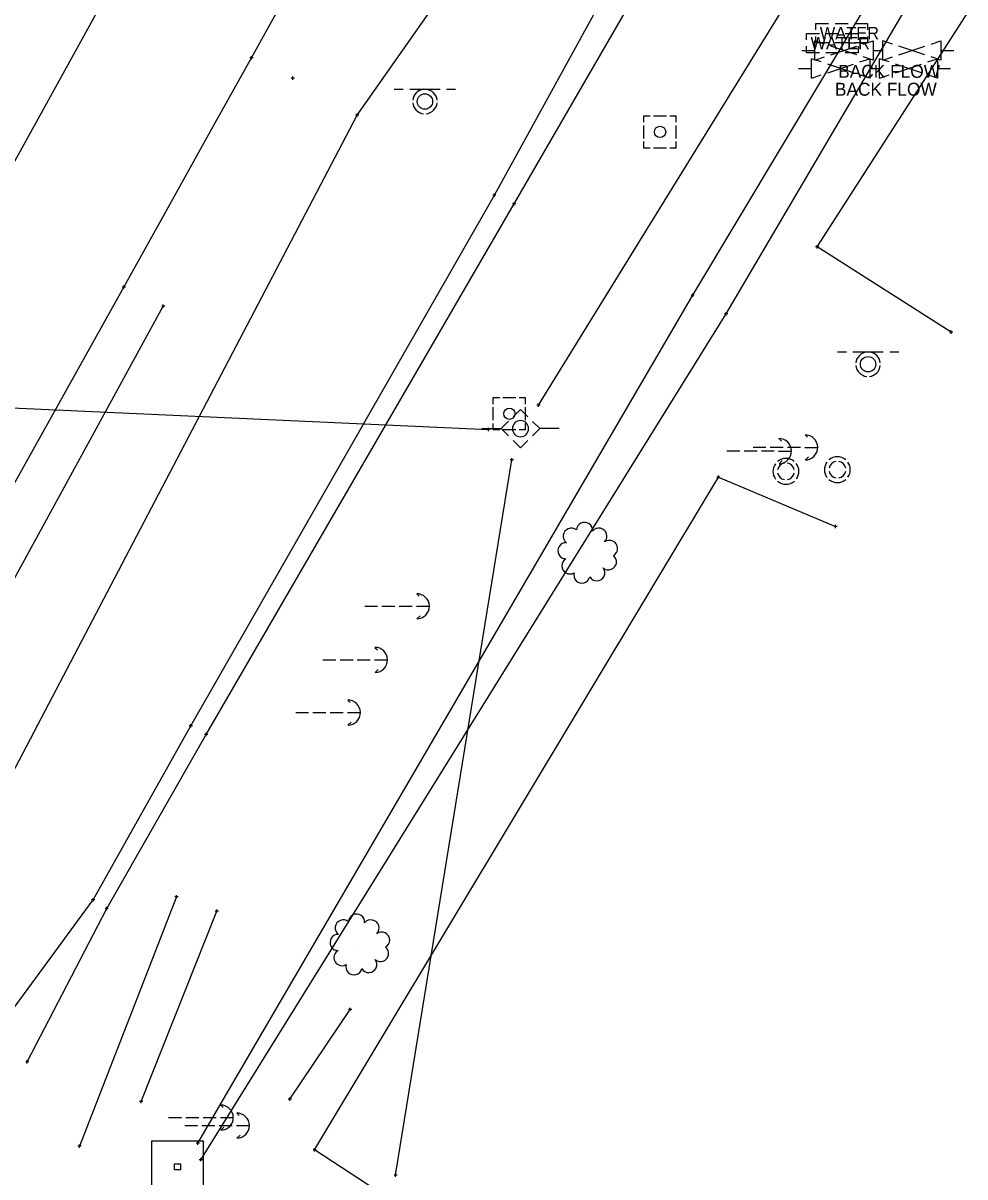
# Model space of a CAD drawing. Extents: x 1954856 to 2011933, y 399149 to 426294.
# Drawn here: x 2006422.5 to 2006495.3, y 401814.9 to 401904.2 of the extents above; entities that cross this region are included whole.
import ezdxf

# ---------------------------------------------------------------- set-up
doc = ezdxf.new("R2010")
doc.units = 0
for name, color, linetype in [('BankMent_ep', 7, 'Continuous'), ('Bollard_ep', 7, 'Continuous'), ('Driveway_ep', 7, 'Continuous'), ('ElecAer_ep', 7, 'Continuous'), ('GuyWireAnchor_ep', 7, 'Continuous'), ('MeterWater_ep', 7, 'Continuous'), ('MonumentCC_ep', 7, 'Continuous'), ('PavtAsphalt_ep', 7, 'Continuous'), ('PMRK_ep', 7, 'Continuous'), ('PointLocator_ep', 7, 'Continuous'), ('PoleShared_ep', 7, 'Continuous'), ('ShldrPaved_ep', 7, 'Continuous'), ('ShrubHedge_ep', 7, 'Continuous'), ('SignMulti_ep', 7, 'Continuous'), ('SignSingle_ep', 7, 'Continuous'), ('TelePed_ep', 7, 'Continuous'), ('TreeOak_ep', 7, 'Continuous'), ('ValveBFP_ep', 7, 'Continuous')]:
    doc.layers.add(name, color=color, linetype=linetype)

msp = doc.modelspace()

# ---------------------------------------------------------------- linework, layer by layer
at = {"layer": 'BankMent_ep'}
for p, q in [((2006448.304, 401897.038), (2006491.823, 401959.082)), ((2006474.251, 401883.114), (2006507.912, 401939.302)), ((2006411.686, 401827.146), (2006448.304, 401897.038)), ((2006435.982, 401817.55), (2006474.251, 401883.114)), ((2006434.331, 401836.603), (2006426.838, 401817.318)), ((2006431.602, 401820.765), (2006437.459, 401835.501))]:
    msp.add_line(p, q, dxfattribs=at)
for points in [[(2006419.806, 401825.353), (2006427.887, 401836.374), (2006435.44, 401849.828), (2006458.914, 401890.845), (2006490.387, 401948.13)], [(2006422.797, 401823.843), (2006428.939, 401835.689), (2006436.625, 401849.155), (2006460.454, 401890.17), (2006493.115, 401946.608)]]:
    msp.add_lwpolyline(points, dxfattribs=at)
at = {"layer": 'Bollard_ep'}
for p, q in [((2006481.46, 401869.499), (2006481.46, 401869.499)), ((2006485.441, 401869.627), (2006485.441, 401869.627))]:
    msp.add_line(p, q, dxfattribs=at)
for centre, radius, start, end in [((2006481.46, 401869.499), 1, 144.06538, 216.38889), ((2006481.46, 401869.499), 1, 49.51375, 130.94053), ((2006481.46, 401869.499), 0.65, 100.12662, 169.87338), ((2006481.46, 401869.499), 0.65, 10.12662, 79.87338), ((2006481.46, 401869.499), 1, 324.06538, 36.38889), ((2006485.441, 401869.627), 1, 144.06538, 216.38889), ((2006485.441, 401869.627), 1, 49.51375, 130.94053), ((2006485.441, 401869.627), 0.65, 100.12662, 169.87338), ((2006485.441, 401869.627), 0.65, 10.12662, 79.87338), ((2006485.441, 401869.627), 1, 324.06538, 36.38889), ((2006481.46, 401869.499), 0.65, 190.12662, 259.87338), ((2006481.46, 401869.499), 0.65, 280.12662, 349.87338), ((2006485.441, 401869.627), 0.65, 190.12662, 259.87338), ((2006485.441, 401869.627), 0.65, 280.12662, 349.87338), ((2006481.46, 401869.499), 1, 229.51375, 310.94053), ((2006485.441, 401869.627), 1, 229.51375, 310.94053)]:
    msp.add_arc(centre, radius, start, end, dxfattribs=at)
at = {"layer": 'Driveway_ep'}
for p, q in [((2006483.871, 401886.858), (2006521.346, 401945.083)), ((2006494.238, 401880.266), (2006483.871, 401886.858))]:
    msp.add_line(p, q, dxfattribs=at)
msp.add_lwpolyline([(2006452.014, 401812.452), (2006445.017, 401817.043), (2006476.238, 401869.059), (2006485.307, 401865.241)], dxfattribs=at)
at = {"layer": 'ElecAer_ep'}
for points in [[(2006462.324, 401874.616), (2006534.112, 401990.988)], [(2006212.402, 401883.926), (2006458.459, 401872.732)], [(2006451.282, 401815.07), (2006460.269, 401870.389)]]:
    msp.add_lwpolyline(points, dxfattribs=at)
at = {"layer": 'GuyWireAnchor_ep'}
for p, q in [((2006480.921, 401872.037), (2006481.114, 401871.844)), ((2006482.943, 401872.321), (2006483.136, 401872.128)), ((2006476.894, 401871.074), (2006477.894, 401871.074)), ((2006478.227, 401871.074), (2006479.227, 401871.074)), ((2006478.916, 401871.358), (2006479.916, 401871.358)), ((2006479.561, 401871.074), (2006480.561, 401871.074)), ((2006480.249, 401871.358), (2006481.249, 401871.358)), ((2006480.894, 401871.064), (2006481.894, 401871.064)), ((2006481.583, 401871.358), (2006482.583, 401871.358)), ((2006481.894, 401871.064), (2006481.894, 401871.064)), ((2006482.916, 401871.348), (2006483.916, 401871.348)), ((2006483.916, 401871.348), (2006483.916, 401871.348)), ((2006480.936, 401870.091), (2006481.174, 401870.324)), ((2006482.958, 401870.375), (2006483.196, 401870.608)), ((2006452.917, 401860.038), (2006453.11, 401859.845)), ((2006448.89, 401859.075), (2006449.89, 401859.075)), ((2006450.223, 401859.075), (2006451.223, 401859.075)), ((2006451.557, 401859.075), (2006452.557, 401859.075)), ((2006452.89, 401859.065), (2006453.89, 401859.065)), ((2006452.932, 401858.092), (2006453.17, 401858.325)), ((2006453.89, 401859.065), (2006453.89, 401859.065)), ((2006449.679, 401855.89), (2006449.872, 401855.697)), ((2006445.652, 401854.927), (2006446.652, 401854.927)), ((2006446.985, 401854.927), (2006447.985, 401854.927)), ((2006448.319, 401854.927), (2006449.319, 401854.927)), ((2006449.652, 401854.917), (2006450.652, 401854.917)), ((2006450.652, 401854.917), (2006450.652, 401854.917)), ((2006449.694, 401853.944), (2006449.932, 401854.177)), ((2006447.58, 401851.818), (2006447.773, 401851.625)), ((2006443.553, 401850.855), (2006444.553, 401850.855)), ((2006444.886, 401850.855), (2006445.886, 401850.855)), ((2006446.22, 401850.855), (2006447.22, 401850.855)), ((2006447.553, 401850.845), (2006448.553, 401850.845)), ((2006448.553, 401850.845), (2006448.553, 401850.845)), ((2006447.595, 401849.872), (2006447.833, 401850.105)), ((2006437.755, 401820.502), (2006437.948, 401820.309)), ((2006438.997, 401819.881), (2006439.19, 401819.688)), ((2006433.728, 401819.539), (2006434.728, 401819.539)), ((2006435.061, 401819.539), (2006436.061, 401819.539)), ((2006436.395, 401819.539), (2006437.395, 401819.539)), ((2006437.728, 401819.529), (2006438.728, 401819.529)), ((2006438.728, 401819.529), (2006438.728, 401819.529)), ((2006434.97, 401818.918), (2006435.97, 401818.918)), ((2006436.303, 401818.918), (2006437.303, 401818.918)), ((2006437.637, 401818.918), (2006438.637, 401818.918)), ((2006437.77, 401818.556), (2006438.008, 401818.789)), ((2006438.97, 401818.908), (2006439.97, 401818.908)), ((2006439.012, 401817.935), (2006439.25, 401818.168)), ((2006439.97, 401818.908), (2006439.97, 401818.908))]:
    msp.add_line(p, q, dxfattribs=at)
for centre in [(2006480.921, 401871.064), (2006482.943, 401871.348), (2006452.917, 401859.065), (2006449.679, 401854.917), (2006447.58, 401850.845), (2006437.755, 401819.529), (2006438.997, 401818.908)]:
    msp.add_arc(centre, 0.973, 271.13997, 90.0059, dxfattribs=at)
at = {"layer": 'MeterWater_ep'}
for p, q in [((2006485.764, 401903.38), (2006485.764, 401903.38)), ((2006485.054, 401902.612), (2006485.054, 401902.612))]:
    msp.add_line(p, q, dxfattribs=at)
for points in [[(2006483.764, 401903.63), (2006483.764, 401904.132), (2006484.764, 401904.132)], [(2006485.264, 401904.132), (2006486.264, 401904.132)], [(2006486.764, 401904.132), (2006487.764, 401904.132), (2006487.764, 401903.63)], [(2006483.054, 401902.862), (2006483.054, 401903.364), (2006484.054, 401903.364)], [(2006484.764, 401902.628), (2006483.764, 401902.628), (2006483.764, 401903.13)], [(2006484.554, 401903.364), (2006485.554, 401903.364)], [(2006486.054, 401903.364), (2006487.054, 401903.364), (2006487.054, 401902.862)], [(2006487.764, 401903.13), (2006487.764, 401902.628), (2006486.764, 401902.628)], [(2006484.054, 401901.86), (2006483.054, 401901.86), (2006483.054, 401902.362)], [(2006486.264, 401902.628), (2006485.264, 401902.628)], [(2006487.054, 401902.362), (2006487.054, 401901.86), (2006486.054, 401901.86)], [(2006485.554, 401901.86), (2006484.554, 401901.86)]]:
    msp.add_lwpolyline(points, dxfattribs=at)
at = {"layer": 'MonumentCC_ep'}
msp.add_line((2006434.415, 401815.715), (2006434.415, 401815.715), dxfattribs=at)
msp.add_lwpolyline([(2006432.413, 401813.713), (2006436.417, 401813.713), (2006436.417, 401817.717), (2006432.413, 401817.717), (2006432.413, 401813.713)], dxfattribs=at)
msp.add_lwpolyline([(2006434.179, 401815.479), (2006434.179, 401815.951), (2006434.651, 401815.951), (2006434.651, 401815.479)], close=True, dxfattribs=at)
at = {"layer": 'PavtAsphalt_ep'}
msp.add_lwpolyline([(2006359.892, 401758.806), (2006367.149, 401771.415), (2006374.339, 401784.062), (2006381.493, 401796.73), (2006387.49, 401807.37), (2006393.481, 401818.013), (2006399.463, 401828.661), (2006409.745, 401847.015), (2006420.006, 401865.38), (2006430.258, 401883.751), (2006433.552, 401889.655), (2006436.844, 401895.559), (2006440.133, 401901.466), (2006453.143, 401924.97), (2006466.038, 401948.539), (2006478.79, 401972.185)], dxfattribs=at)
at = {"layer": 'PMRK_ep'}
msp.add_lwpolyline([(2006391.583, 401838.69), (2006429.54, 401907.466), (2006467.997, 401977.948), (2006496.741, 402032.181)], dxfattribs=at)
at = {"layer": 'PointLocator_ep'}
for p, q in [((2006440.258, 401901.466), (2006440.008, 401901.466)), ((2006440.133, 401901.341), (2006440.133, 401901.591)), ((2006440.133, 401901.466), (2006440.133, 401901.466)), ((2006443.458, 401899.903), (2006443.208, 401899.903)), ((2006443.333, 401899.778), (2006443.333, 401900.028)), ((2006443.333, 401899.903), (2006443.333, 401899.903)), ((2006448.429, 401897.038), (2006448.179, 401897.038)), ((2006448.304, 401896.913), (2006448.304, 401897.163)), ((2006448.304, 401897.038), (2006448.304, 401897.038)), ((2006459.039, 401890.845), (2006458.789, 401890.845)), ((2006458.914, 401890.72), (2006458.914, 401890.97)), ((2006458.914, 401890.845), (2006458.914, 401890.845)), ((2006460.579, 401890.17), (2006460.329, 401890.17)), ((2006460.454, 401890.045), (2006460.454, 401890.295)), ((2006460.454, 401890.17), (2006460.454, 401890.17)), ((2006483.996, 401886.858), (2006483.746, 401886.858)), ((2006483.871, 401886.733), (2006483.871, 401886.983)), ((2006483.871, 401886.858), (2006483.871, 401886.858)), ((2006430.383, 401883.751), (2006430.133, 401883.751)), ((2006430.258, 401883.626), (2006430.258, 401883.876)), ((2006430.258, 401883.751), (2006430.258, 401883.751)), ((2006474.251, 401882.989), (2006474.251, 401883.239)), ((2006433.314, 401882.151), (2006433.314, 401882.401)), ((2006474.376, 401883.114), (2006474.126, 401883.114)), ((2006474.251, 401883.114), (2006474.251, 401883.114)), ((2006433.439, 401882.276), (2006433.189, 401882.276)), ((2006433.314, 401882.276), (2006433.314, 401882.276)), ((2006476.957, 401881.678), (2006476.707, 401881.678)), ((2006476.832, 401881.553), (2006476.832, 401881.803)), ((2006476.832, 401881.678), (2006476.832, 401881.678)), ((2006494.363, 401880.266), (2006494.113, 401880.266)), ((2006494.238, 401880.141), (2006494.238, 401880.391)), ((2006494.238, 401880.266), (2006494.238, 401880.266)), ((2006462.449, 401874.616), (2006462.199, 401874.616)), ((2006462.324, 401874.491), (2006462.324, 401874.741)), ((2006462.324, 401874.616), (2006462.324, 401874.616)), ((2006458.584, 401872.732), (2006458.334, 401872.732)), ((2006458.459, 401872.607), (2006458.459, 401872.857)), ((2006458.459, 401872.732), (2006458.459, 401872.732)), ((2006460.394, 401870.389), (2006460.144, 401870.389)), ((2006460.269, 401870.264), (2006460.269, 401870.514)), ((2006460.269, 401870.389), (2006460.269, 401870.389)), ((2006476.363, 401869.059), (2006476.113, 401869.059)), ((2006476.238, 401868.934), (2006476.238, 401869.184)), ((2006476.238, 401869.059), (2006476.238, 401869.059)), ((2006485.307, 401865.116), (2006485.307, 401865.366)), ((2006485.432, 401865.241), (2006485.182, 401865.241)), ((2006485.307, 401865.241), (2006485.307, 401865.241)), ((2006435.565, 401849.828), (2006435.315, 401849.828)), ((2006435.44, 401849.703), (2006435.44, 401849.953)), ((2006435.44, 401849.828), (2006435.44, 401849.828)), ((2006436.75, 401849.155), (2006436.5, 401849.155)), ((2006436.625, 401849.03), (2006436.625, 401849.28)), ((2006436.625, 401849.155), (2006436.625, 401849.155)), ((2006428.012, 401836.374), (2006427.762, 401836.374)), ((2006427.887, 401836.249), (2006427.887, 401836.499)), ((2006427.887, 401836.374), (2006427.887, 401836.374)), ((2006434.456, 401836.603), (2006434.206, 401836.603)), ((2006434.331, 401836.478), (2006434.331, 401836.728)), ((2006434.331, 401836.603), (2006434.331, 401836.603)), ((2006429.064, 401835.689), (2006428.814, 401835.689)), ((2006428.939, 401835.564), (2006428.939, 401835.814)), ((2006428.939, 401835.689), (2006428.939, 401835.689)), ((2006437.584, 401835.501), (2006437.334, 401835.501)), ((2006437.459, 401835.376), (2006437.459, 401835.626)), ((2006437.459, 401835.501), (2006437.459, 401835.501)), ((2006447.889, 401827.898), (2006447.639, 401827.898)), ((2006447.764, 401827.773), (2006447.764, 401828.023)), ((2006447.764, 401827.898), (2006447.764, 401827.898)), ((2006422.922, 401823.843), (2006422.672, 401823.843)), ((2006422.797, 401823.718), (2006422.797, 401823.968)), ((2006422.797, 401823.843), (2006422.797, 401823.843)), ((2006431.727, 401820.765), (2006431.477, 401820.765)), ((2006431.602, 401820.64), (2006431.602, 401820.89)), ((2006431.602, 401820.765), (2006431.602, 401820.765)), ((2006443.218, 401820.954), (2006442.968, 401820.954)), ((2006443.093, 401820.829), (2006443.093, 401821.079)), ((2006443.093, 401820.954), (2006443.093, 401820.954)), ((2006426.963, 401817.318), (2006426.713, 401817.318)), ((2006426.838, 401817.193), (2006426.838, 401817.443)), ((2006426.838, 401817.318), (2006426.838, 401817.318)), ((2006436.107, 401817.55), (2006435.857, 401817.55)), ((2006435.982, 401817.425), (2006435.982, 401817.675)), ((2006435.982, 401817.55), (2006435.982, 401817.55)), ((2006436.216, 401816.151), (2006436.216, 401816.401)), ((2006445.142, 401817.043), (2006444.892, 401817.043)), ((2006445.017, 401816.918), (2006445.017, 401817.168)), ((2006445.017, 401817.043), (2006445.017, 401817.043)), ((2006436.341, 401816.276), (2006436.091, 401816.276)), ((2006436.216, 401816.276), (2006436.216, 401816.276)), ((2006451.407, 401815.07), (2006451.157, 401815.07)), ((2006451.282, 401814.945), (2006451.282, 401815.195)), ((2006451.282, 401815.07), (2006451.282, 401815.07))]:
    msp.add_line(p, q, dxfattribs=at)
at = {"layer": 'PoleShared_ep'}
for p, q in [((2006457.948, 401872.798), (2006459.448, 401872.798)), ((2006459.448, 401872.798), (2006460.015, 401873.365)), ((2006460.01, 401872.237), (2006459.448, 401872.798)), ((2006460.936, 401872.798), (2006460.936, 401872.798)), ((2006463.924, 401872.798), (2006462.424, 401872.798))]:
    msp.add_line(p, q, dxfattribs=at)
for points in [[(2006460.371, 401873.721), (2006460.936, 401874.286), (2006461.503, 401873.719)], [(2006461.858, 401873.364), (2006462.424, 401872.798), (2006461.857, 401872.231)], [(2006461.503, 401871.877), (2006460.936, 401871.31), (2006460.369, 401871.877)]]:
    msp.add_lwpolyline(points, dxfattribs=at)
for start, end in [(90, 270), (270, 90)]:
    msp.add_arc((2006460.936, 401872.798), 0.625, start, end, dxfattribs=at)
at = {"layer": 'ShldrPaved_ep'}
msp.add_line((2006419.386, 401856.817), (2006433.314, 401882.276), dxfattribs=at)
at = {"layer": 'ShrubHedge_ep'}
msp.add_lwpolyline([(2006436.216, 401816.276), (2006476.832, 401881.678), (2006513.86, 401944.624)], dxfattribs=at)
at = {"layer": 'SignMulti_ep'}
msp.add_lwpolyline([(2006443.093, 401820.954), (2006447.764, 401827.898)], dxfattribs=at)
at = {"layer": 'SignSingle_ep'}
for p, q in [((2006451.172, 401899.042), (2006451.872, 401899.042)), ((2006452.372, 401899.042), (2006454.722, 401899.042)), ((2006455.222, 401899.042), (2006455.922, 401899.042)), ((2006453.547, 401898.092), (2006453.547, 401898.092)), ((2006485.437, 401878.729), (2006486.137, 401878.729)), ((2006486.637, 401878.729), (2006488.987, 401878.729)), ((2006489.487, 401878.729), (2006490.187, 401878.729)), ((2006487.812, 401877.779), (2006487.812, 401877.779))]:
    msp.add_line(p, q, dxfattribs=at)
for centre in [(2006453.547, 401898.092), (2006487.812, 401877.779)]:
    msp.add_circle(centre, 0.594, dxfattribs=at)
for centre, start, end in [((2006453.547, 401898.092), 96.04233, 173.95767), ((2006453.547, 401898.092), 6.04233, 83.95767), ((2006453.547, 401898.092), 186.04233, 263.95767), ((2006453.547, 401898.092), 276.04233, 353.95767), ((2006487.812, 401877.779), 96.04233, 173.95767), ((2006487.812, 401877.779), 6.04233, 83.95767), ((2006487.812, 401877.779), 186.04233, 263.95767), ((2006487.812, 401877.779), 276.04233, 353.95767)]:
    msp.add_arc(centre, 0.95, start, end, dxfattribs=at)
at = {"layer": 'TelePed_ep'}
for p, q in [((2006470.474, 401896.993), (2006470.974, 401896.993)), ((2006470.474, 401896.493), (2006470.474, 401896.993)), ((2006471.224, 401896.993), (2006472.224, 401896.993)), ((2006472.474, 401896.993), (2006472.974, 401896.993)), ((2006472.974, 401896.493), (2006472.974, 401896.993)), ((2006470.474, 401895.243), (2006470.474, 401896.243)), ((2006471.724, 401895.743), (2006471.724, 401895.743)), ((2006472.974, 401895.243), (2006472.974, 401896.243)), ((2006470.474, 401894.493), (2006470.474, 401894.993)), ((2006472.974, 401894.493), (2006472.974, 401894.993)), ((2006470.974, 401894.493), (2006470.474, 401894.493)), ((2006472.224, 401894.493), (2006471.224, 401894.493)), ((2006472.974, 401894.493), (2006472.474, 401894.493)), ((2006458.831, 401875.201), (2006459.331, 401875.201)), ((2006458.831, 401874.701), (2006458.831, 401875.201)), ((2006459.581, 401875.201), (2006460.581, 401875.201)), ((2006460.831, 401875.201), (2006461.331, 401875.201)), ((2006461.331, 401874.701), (2006461.331, 401875.201)), ((2006458.831, 401873.451), (2006458.831, 401874.451)), ((2006461.331, 401873.451), (2006461.331, 401874.451)), ((2006460.081, 401873.951), (2006460.081, 401873.951)), ((2006458.831, 401872.701), (2006458.831, 401873.201)), ((2006459.331, 401872.701), (2006458.831, 401872.701)), ((2006460.581, 401872.701), (2006459.581, 401872.701)), ((2006461.331, 401872.701), (2006460.831, 401872.701)), ((2006461.331, 401872.701), (2006461.331, 401873.201))]:
    msp.add_line(p, q, dxfattribs=at)
for centre in [(2006471.724, 401895.743), (2006460.081, 401873.951)]:
    msp.add_circle(centre, 0.438, dxfattribs=at)
at = {"layer": 'TreeOak_ep'}
for p, q in [((2006466.096, 401863.205), (2006466.096, 401863.205)), ((2006448.47, 401832.918), (2006448.47, 401832.918))]:
    msp.add_line(p, q, dxfattribs=at)
for centre, radius, start, end in [((2006465.885, 401864.928), 0.629, 355.39425, 176.65487), ((2006464.861, 401864.482), 0.624, 50.71855, 233.08403), ((2006466.997, 401864.48), 0.627, 315.08978, 140.68326), ((2006464.457, 401863.358), 0.625, 87.30955, 269.56183), ((2006467.82, 401863.539), 0.626, 299.43541, 127.26128), ((2006464.76, 401862.188), 0.626, 119.4469, 301.0197), ((2006467.737, 401862.508), 0.623, 229.28724, 51.20251), ((2006466.828, 401861.659), 0.628, 211.18773, 36.81995), ((2006465.684, 401861.482), 0.625, 164.28711, 346.27665), ((2006448.259, 401834.641), 0.629, 355.39425, 176.65487), ((2006447.235, 401834.195), 0.624, 50.71855, 233.08403), ((2006449.371, 401834.193), 0.627, 315.08978, 140.68326), ((2006446.831, 401833.071), 0.625, 87.30955, 269.56183), ((2006450.194, 401833.252), 0.626, 299.43541, 127.26128), ((2006447.134, 401831.901), 0.626, 119.4469, 301.0197), ((2006450.111, 401832.221), 0.623, 229.28724, 51.20251), ((2006449.202, 401831.372), 0.628, 211.18773, 36.81995), ((2006448.058, 401831.195), 0.625, 164.28711, 346.27665)]:
    msp.add_arc(centre, radius, start, end, dxfattribs=at)
at = {"layer": 'ValveBFP_ep'}
for p, q in [((2006482.698, 401902.037), (2006483.698, 401902.037)), ((2006483.698, 401901.287), (2006483.698, 401902.787)), ((2006484.444, 401902.538), (2006483.698, 401902.787)), ((2006486.944, 401901.705), (2006484.944, 401902.372)), ((2006484.944, 401901.702), (2006486.944, 401902.369)), ((2006487.444, 401902.536), (2006488.198, 401902.787)), ((2006488.198, 401902.787), (2006488.198, 401901.287)), ((2006488.198, 401902.037), (2006488.948, 401902.037)), ((2006488.573, 401902.037), (2006488.573, 401902.037)), ((2006488.948, 401901.287), (2006488.948, 401902.787)), ((2006489.698, 401902.537), (2006488.948, 401902.787)), ((2006490.198, 401901.704), (2006492.198, 401902.37)), ((2006492.198, 401901.704), (2006490.198, 401902.37)), ((2006492.698, 401902.537), (2006493.448, 401902.787)), ((2006493.448, 401902.787), (2006493.448, 401901.287)), ((2006493.448, 401902.037), (2006494.448, 401902.037)), ((2006483.443, 401899.904), (2006483.443, 401901.404)), ((2006484.189, 401901.155), (2006483.443, 401901.404)), ((2006483.698, 401901.287), (2006484.444, 401901.536)), ((2006487.189, 401901.153), (2006487.943, 401901.404)), ((2006488.198, 401901.287), (2006487.444, 401901.538)), ((2006487.943, 401901.404), (2006487.943, 401899.904)), ((2006488.693, 401899.904), (2006488.693, 401901.404)), ((2006489.443, 401901.154), (2006488.693, 401901.404)), ((2006488.948, 401901.287), (2006489.698, 401901.537)), ((2006492.443, 401901.154), (2006493.193, 401901.404)), ((2006493.448, 401901.287), (2006492.698, 401901.537)), ((2006493.193, 401901.404), (2006493.193, 401899.904)), ((2006482.443, 401900.654), (2006483.443, 401900.654)), ((2006483.443, 401899.904), (2006484.189, 401900.153)), ((2006486.689, 401900.322), (2006484.689, 401900.989)), ((2006484.689, 401900.319), (2006486.689, 401900.986)), ((2006487.943, 401899.904), (2006487.189, 401900.155)), ((2006487.943, 401900.654), (2006488.693, 401900.654)), ((2006488.318, 401900.654), (2006488.318, 401900.654)), ((2006488.693, 401899.904), (2006489.443, 401900.154)), ((2006489.943, 401900.321), (2006491.943, 401900.987)), ((2006491.943, 401900.321), (2006489.943, 401900.987)), ((2006493.193, 401899.904), (2006492.443, 401900.154)), ((2006493.193, 401900.654), (2006494.193, 401900.654))]:
    msp.add_line(p, q, dxfattribs=at)

# ---------------------------------------------------------------- texts
at = {"layer": 'MeterWater_ep'}
for p in [(2006484.075, 401902.908), (2006483.365, 401902.14)]:
    msp.add_text('WATER', height=0.95, dxfattribs=at).set_placement(p)
at = {"layer": 'ValveBFP_ep'}
for p in [(2006485.504, 401899.925), (2006485.249, 401898.542)]:
    msp.add_text('BACK FLOW', height=1, dxfattribs=at).set_placement(p)

doc.saveas('drawing.dxf')
